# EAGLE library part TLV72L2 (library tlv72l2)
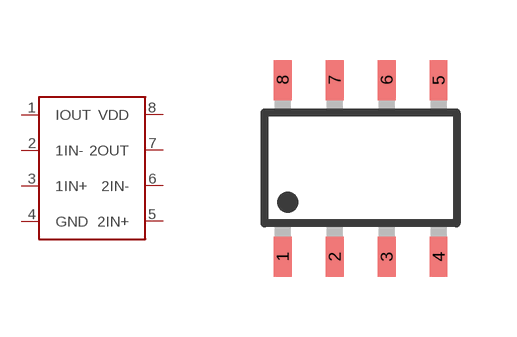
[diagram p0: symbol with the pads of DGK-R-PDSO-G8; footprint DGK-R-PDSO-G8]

Designator prefix -

## TLV72L2  [DGK-R-PDSO-G8]
1  IOUT  out
2  1IN-  in
3  1IN+  in
4  GND  pwr
5  2IN+  in
6  2IN-  in
7  2OUT  out
8  VDD  pwr

## Footprint DGK-R-PDSO-G8 (pad centres in mm)
DGK (R-PDSO-G8) Source: http://focus.ti.com/lit/ds/symlink/tps77333.pdf
smd 0.45 x 1: 1 -1.95,-2.21; 2 -0.65,-2.21; 3 0.65,-2.21; 4 1.95,-2.21; 5 1.95,2.21; 6 0.65,2.21; 7 -0.65,2.21; 8 -1.95,2.21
